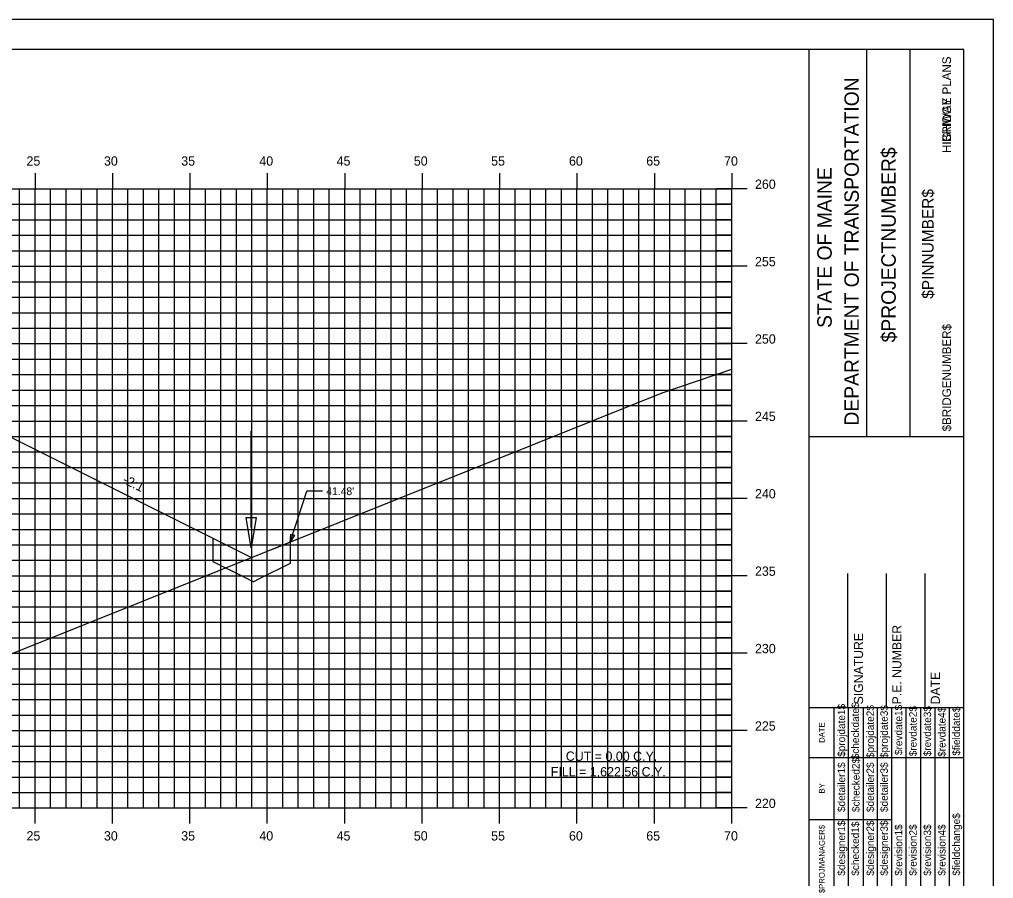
# Model space of a CAD drawing. Extents: x 1160718 to 1173142, y 616002 to 617630.
# Drawn here: x 1169986.4 to 1170049.3, y 616668.4 to 616723.9 of the extents above; entities that cross this region are included whole.
import ezdxf

# ---------------------------------------------------------------- set-up
doc = ezdxf.new("R2010")
doc.units = 0
for name, color, linetype in [('ANNOTATION', 7, 'Continuous'), ('BORDER', 7, 'Continuous'), ('BRIDGE_TITLE', 7, 'Continuous'), ('D_Drainage_Ditch_Line', 7, 'Continuous'), ('D_Roadway_SubGrade', 7, 'Continuous'), ('H_V ANNOTATION', 7, 'Continuous'), ('HIGHWAY_TITLE', 7, 'Continuous'), ('MAJOR', 7, 'Continuous'), ('MINOR', 7, 'Continuous'), ('PLOT BOUNDARY', 7, 'Continuous'), ('S_Roadway_Centerline', 7, 'Continuous')]:
    doc.layers.add(name, color=color, linetype=linetype)

msp = doc.modelspace()

# ---------------------------------------------------------------- linework, layer by layer
at = {"layer": 'ANNOTATION'}
for p in [(1170003.869, 616690.109), (1170005.953, 616693.39)]:
    msp.add_line(p, (1170004.953, 616693.39), dxfattribs=at)
for points in [[(1169998.869, 616690.357), (1170001.369, 616689.107), (1170003.869, 616690.109), (1170003.869, 616688.726), (1170001.869, 616687.726), (1170001.5, 616687.541)], [(1169998.869, 616690.357), (1169998.869, 616688.857), (1170000.869, 616687.857), (1170001.5, 616687.541)]]:
    msp.add_lwpolyline(points, dxfattribs=at)
msp.add_lwpolyline([(1170004.144, 616690.545), (1170003.869, 616690.109), (1170003.907, 616690.623)], close=True, dxfattribs=at)
at = {"layer": 'BORDER'}
for p, q in [((1170047.394, 616721.928), (1169887.394, 616721.928)), ((1170037.394, 616616.931), (1170037.394, 616721.931)), ((1170041.123, 616696.925), (1170041.123, 616721.925)), ((1170043.918, 616696.925), (1170043.918, 616721.925)), ((1170047.394, 616616.931), (1170047.394, 616721.931)), ((1170037.395, 616696.923), (1170047.394, 616696.923)), ((1170039.894, 616679.431), (1170039.894, 616688.079)), ((1170042.394, 616679.431), (1170042.394, 616688.079)), ((1170044.894, 616679.431), (1170044.894, 616688.079)), ((1170037.394, 616679.431), (1170047.394, 616679.431))]:
    msp.add_line(p, q, dxfattribs=at)
for points in [[(1170039.009, 616676.181), (1170039.009, 616679.431)], [(1170039.942, 616661.934), (1170039.942, 616679.431)], [(1170040.873, 616679.431), (1170040.873, 616661.934)], [(1170041.805, 616661.934), (1170041.805, 616679.431)], [(1170042.737, 616661.934), (1170042.737, 616679.431)], [(1170043.668, 616661.934), (1170043.668, 616679.431)], [(1170044.6, 616661.934), (1170044.6, 616679.431)], [(1170045.532, 616661.934), (1170045.532, 616679.431)], [(1170046.463, 616661.934), (1170046.463, 616679.431)], [(1170039.01, 616661.934), (1170039.01, 616678.725)], [(1170037.394, 616676.181), (1170047.394, 616676.181)], [(1170037.394, 616672.181), (1170039.01, 616672.181)], [(1170039.009, 616672.181), (1170042.736, 616672.181)]]:
    msp.add_lwpolyline(points, dxfattribs=at)
at = {"layer": 'D_Drainage_Ditch_Line'}
msp.add_line((1170001.346, 616691.04), (1170001.347, 616697.283), dxfattribs=at)
msp.add_lwpolyline([(1170001.018, 616691.696), (1170001.675, 616691.696), (1170001.347, 616689.727)], close=True, dxfattribs=at)
at = {"layer": 'D_Roadway_SubGrade'}
msp.add_line((1169982.394, 616698.594), (1170001.369, 616689.107), dxfattribs=at)
at = {"layer": 'MAJOR'}
for p, q in [((1169987.394, 616713.93), (1169987.394, 616712.928)), ((1169992.394, 616713.93), (1169992.394, 616712.928)), ((1169997.394, 616713.93), (1169997.394, 616712.928)), ((1170002.394, 616713.93), (1170002.394, 616712.928)), ((1170007.394, 616713.93), (1170007.394, 616712.928)), ((1170012.394, 616713.93), (1170012.394, 616712.928)), ((1170017.394, 616713.93), (1170017.394, 616712.928)), ((1170022.394, 616713.93), (1170022.394, 616712.928)), ((1170027.394, 616713.93), (1170027.394, 616712.928)), ((1170032.394, 616713.93), (1170032.394, 616712.928)), ((1169892.394, 616712.928), (1170032.394, 616712.928)), ((1169892.394, 616712.928), (1170032.394, 616712.928)), ((1169987.394, 616672.928), (1169987.394, 616712.928)), ((1169992.394, 616672.928), (1169992.394, 616712.928)), ((1169997.394, 616672.928), (1169997.394, 616712.928)), ((1170002.394, 616672.928), (1170002.394, 616712.928)), ((1170007.394, 616672.928), (1170007.394, 616712.928)), ((1170012.394, 616672.928), (1170012.394, 616712.928)), ((1170017.394, 616672.928), (1170017.394, 616712.928)), ((1170022.394, 616672.928), (1170022.394, 616712.928)), ((1170027.394, 616672.928), (1170027.394, 616712.928)), ((1170033.396, 616712.928), (1170031.392, 616712.928)), ((1170032.394, 616672.928), (1170032.394, 616712.928)), ((1170032.394, 616672.928), (1170032.394, 616712.928)), ((1169892.394, 616707.928), (1170032.394, 616707.928)), ((1170033.396, 616707.928), (1170031.392, 616707.928)), ((1169892.394, 616702.928), (1170032.394, 616702.928)), ((1170033.396, 616702.928), (1170031.392, 616702.928)), ((1169892.394, 616697.928), (1170032.394, 616697.928)), ((1170033.396, 616697.928), (1170031.392, 616697.928)), ((1169892.394, 616692.928), (1170032.394, 616692.928)), ((1170033.396, 616692.928), (1170031.392, 616692.928)), ((1169892.394, 616687.928), (1170032.394, 616687.928)), ((1170033.396, 616687.928), (1170031.392, 616687.928)), ((1169892.394, 616682.928), (1170032.394, 616682.928)), ((1170033.396, 616682.928), (1170031.392, 616682.928)), ((1169892.394, 616677.928), (1170032.394, 616677.928)), ((1170033.396, 616677.928), (1170031.392, 616677.928)), ((1169892.394, 616672.928), (1170032.394, 616672.928)), ((1169892.394, 616672.928), (1170032.394, 616672.928)), ((1169987.394, 616671.926), (1169987.394, 616672.928)), ((1169992.394, 616671.926), (1169992.394, 616672.928)), ((1169997.394, 616671.926), (1169997.394, 616672.928)), ((1170002.394, 616671.926), (1170002.394, 616672.928)), ((1170007.394, 616671.926), (1170007.394, 616672.928)), ((1170012.394, 616671.926), (1170012.394, 616672.928)), ((1170017.394, 616671.926), (1170017.394, 616672.928)), ((1170022.394, 616671.926), (1170022.394, 616672.928)), ((1170027.394, 616671.926), (1170027.394, 616672.928)), ((1170033.396, 616672.928), (1170031.392, 616672.928)), ((1170032.394, 616671.926), (1170032.394, 616672.928))]:
    msp.add_line(p, q, dxfattribs=at)
at = {"layer": 'MINOR'}
for p, q in [((1169986.394, 616672.928), (1169986.394, 616712.928)), ((1169988.394, 616672.928), (1169988.394, 616712.928)), ((1169989.394, 616672.928), (1169989.394, 616712.928)), ((1169990.394, 616672.928), (1169990.394, 616712.928)), ((1169991.394, 616672.928), (1169991.394, 616712.928)), ((1169993.394, 616672.928), (1169993.394, 616712.928)), ((1169994.394, 616672.928), (1169994.394, 616712.928)), ((1169995.394, 616672.928), (1169995.394, 616712.928)), ((1169996.394, 616672.928), (1169996.394, 616712.928)), ((1169998.394, 616672.928), (1169998.394, 616712.928)), ((1169999.394, 616672.928), (1169999.394, 616712.928)), ((1170000.394, 616672.928), (1170000.394, 616712.928)), ((1170001.394, 616672.928), (1170001.394, 616712.928)), ((1170003.394, 616672.928), (1170003.394, 616712.928)), ((1170004.394, 616672.928), (1170004.394, 616712.928)), ((1170005.394, 616672.928), (1170005.394, 616712.928)), ((1170006.394, 616672.928), (1170006.394, 616712.928)), ((1170008.394, 616672.928), (1170008.394, 616712.928)), ((1170009.394, 616672.928), (1170009.394, 616712.928)), ((1170010.394, 616672.928), (1170010.394, 616712.928)), ((1170011.394, 616672.928), (1170011.394, 616712.928)), ((1170013.394, 616672.928), (1170013.394, 616712.928)), ((1170014.394, 616672.928), (1170014.394, 616712.928)), ((1170015.394, 616672.928), (1170015.394, 616712.928)), ((1170016.394, 616672.928), (1170016.394, 616712.928)), ((1170018.394, 616672.928), (1170018.394, 616712.928)), ((1170019.394, 616672.928), (1170019.394, 616712.928)), ((1170020.394, 616672.928), (1170020.394, 616712.928)), ((1170021.394, 616672.928), (1170021.394, 616712.928)), ((1170023.394, 616672.928), (1170023.394, 616712.928)), ((1170024.394, 616672.928), (1170024.394, 616712.928)), ((1170025.394, 616672.928), (1170025.394, 616712.928)), ((1170026.394, 616672.928), (1170026.394, 616712.928)), ((1170028.394, 616672.928), (1170028.394, 616712.928)), ((1170029.394, 616672.928), (1170029.394, 616712.928)), ((1170030.394, 616672.928), (1170030.394, 616712.928)), ((1170031.394, 616672.928), (1170031.394, 616712.928)), ((1169892.394, 616711.928), (1170032.394, 616711.928)), ((1170032.394, 616711.928), (1170031.392, 616711.928)), ((1169892.394, 616710.928), (1170032.394, 616710.928)), ((1170032.394, 616710.928), (1170031.392, 616710.928)), ((1169892.394, 616709.928), (1170032.394, 616709.928)), ((1170032.394, 616709.928), (1170031.392, 616709.928)), ((1169892.394, 616708.928), (1170032.394, 616708.928)), ((1170032.394, 616708.928), (1170031.392, 616708.928)), ((1169892.394, 616706.928), (1170032.394, 616706.928)), ((1170032.394, 616706.928), (1170031.392, 616706.928)), ((1169892.394, 616705.928), (1170032.394, 616705.928)), ((1170032.394, 616705.928), (1170031.392, 616705.928)), ((1169892.394, 616704.928), (1170032.394, 616704.928)), ((1170032.394, 616704.928), (1170031.392, 616704.928)), ((1169892.394, 616703.928), (1170032.394, 616703.928)), ((1170032.394, 616703.928), (1170031.392, 616703.928)), ((1169892.394, 616701.928), (1170032.394, 616701.928)), ((1170032.394, 616701.928), (1170031.392, 616701.928)), ((1169892.394, 616700.928), (1170032.394, 616700.928)), ((1170032.394, 616700.928), (1170031.392, 616700.928)), ((1169892.394, 616699.928), (1170032.394, 616699.928)), ((1170032.394, 616699.928), (1170031.392, 616699.928)), ((1169892.394, 616698.928), (1170032.394, 616698.928)), ((1170032.394, 616698.928), (1170031.392, 616698.928)), ((1169892.394, 616696.928), (1170032.394, 616696.928)), ((1170032.394, 616696.928), (1170031.392, 616696.928)), ((1169892.394, 616695.928), (1170032.394, 616695.928)), ((1170032.394, 616695.928), (1170031.392, 616695.928)), ((1169892.394, 616694.928), (1170032.394, 616694.928)), ((1170032.394, 616694.928), (1170031.392, 616694.928)), ((1169892.394, 616693.928), (1170032.394, 616693.928)), ((1170032.394, 616693.928), (1170031.392, 616693.928)), ((1169892.394, 616691.928), (1170032.394, 616691.928)), ((1170032.394, 616691.928), (1170031.392, 616691.928)), ((1169892.394, 616690.928), (1170032.394, 616690.928)), ((1170032.394, 616690.928), (1170031.392, 616690.928)), ((1169892.394, 616689.928), (1170032.394, 616689.928)), ((1170032.394, 616689.928), (1170031.392, 616689.928)), ((1169892.394, 616688.928), (1170032.394, 616688.928)), ((1170032.394, 616688.928), (1170031.392, 616688.928)), ((1169892.394, 616686.928), (1170032.394, 616686.928)), ((1170032.394, 616686.928), (1170031.392, 616686.928)), ((1169892.394, 616685.928), (1170032.394, 616685.928)), ((1170032.394, 616685.928), (1170031.392, 616685.928)), ((1169892.394, 616684.928), (1170032.394, 616684.928)), ((1170032.394, 616684.928), (1170031.392, 616684.928)), ((1169892.394, 616683.928), (1170032.394, 616683.928)), ((1170032.394, 616683.928), (1170031.392, 616683.928)), ((1169892.394, 616681.928), (1170032.394, 616681.928)), ((1170032.394, 616681.928), (1170031.392, 616681.928)), ((1169892.394, 616680.928), (1170032.394, 616680.928)), ((1170032.394, 616680.928), (1170031.392, 616680.928)), ((1169892.394, 616679.928), (1170032.394, 616679.928)), ((1170032.394, 616679.928), (1170031.392, 616679.928)), ((1169892.394, 616678.928), (1170032.394, 616678.928)), ((1170032.394, 616678.928), (1170031.392, 616678.928)), ((1169892.394, 616676.928), (1170032.394, 616676.928)), ((1170032.394, 616676.928), (1170031.392, 616676.928)), ((1169892.394, 616675.928), (1170032.394, 616675.928)), ((1170032.394, 616675.928), (1170031.392, 616675.928)), ((1169892.394, 616674.928), (1170032.394, 616674.928)), ((1170032.394, 616674.928), (1170031.392, 616674.928)), ((1169892.394, 616673.928), (1170032.394, 616673.928)), ((1170032.394, 616673.928), (1170031.392, 616673.928))]:
    msp.add_line(p, q, dxfattribs=at)
at = {"layer": 'PLOT BOUNDARY'}
msp.add_lwpolyline([(1169879.301, 616613.869), (1170049.301, 616613.869), (1170049.301, 616723.869), (1169879.301, 616723.869)], close=True, dxfattribs=at)
at = {"layer": 'S_Roadway_Centerline'}
msp.add_lwpolyline([(1169892.394, 616704.998), (1169908.245, 616697.269), (1169915.124, 616693.694), (1169944.356, 616683.254), (1169956.998, 616682.309), (1169964.821, 616682.573), (1169971.903, 616683.316), (1169981.644, 616681.197), (1170027.895, 616699.745), (1170032.394, 616701.285)], dxfattribs=at)

# ---------------------------------------------------------------- texts
at = {"layer": 'ANNOTATION'}
for s, rotation, p in [('-2:1', 333.43495, (1169993.005, 616693.951)), ('CUT = 0.00 C.Y.', 359.92408, (1170021.674, 616675.978)), ('FILL = 1,622.56 C.Y.', 359.92408, (1170020.704, 616674.977))]:
    msp.add_text(s, height=0.6, rotation=rotation, dxfattribs=at).set_placement(p)
msp.add_text("41.48'", height=0.5, dxfattribs=at).set_placement((1170006.203, 616693.14))
at = {"layer": 'BORDER'}
for s, height, p in [('DEPARTMENT OF TRANSPORTATION', 0.93176, (1170040.601, 616697.634)), ('$PROJECTNUMBER$', 0.93176, (1170042.986, 616703.008)), ('STATE OF MAINE', 0.93176, (1170038.849, 616703.94)), ('$PINNUMBER$', 0.74527, (1170045.431, 616705.825)), ('P.E. NUMBER', 0.59055, (1170043.355, 616679.624)), ('SIGNATURE', 0.5906, (1170040.875, 616679.624)), ('DATE', 0.5906, (1170045.835, 616679.624)), ('$projdate1$', 0.48455, (1170039.717, 616676.232)), ('$checkdate$', 0.48455, (1170040.612, 616676.074)), ('$projdate2$', 0.48455, (1170041.58, 616676.153)), ('$projdate3$', 0.48455, (1170042.475, 616676.153)), ('$revdate1$', 0.4845, (1170043.407, 616676.35)), ('$revdate2$', 0.4845, (1170044.338, 616676.271)), ('$revdate3$', 0.4845, (1170045.27, 616676.271)), ('$revdate4$', 0.4845, (1170046.202, 616676.232)), ('$fielddate$', 0.48455, (1170047.133, 616676.31)), ('DATE', 0.3714, (1170038.398, 616677.137)), ('$detailer1$', 0.48455, (1170039.717, 616672.667)), ('$checked2$', 0.4845, (1170040.649, 616672.667)), ('$detailer2$', 0.48455, (1170041.58, 616672.667)), ('$detailer3$', 0.48455, (1170042.475, 616672.667)), ('BY', 0.3714, (1170038.398, 616673.866)), ('$fieldchange$', 0.48455, (1170047.133, 616668.555)), ('$PROJMANAGER$', 0.37275, (1170038.398, 616667.426)), ('$designer1$', 0.48455, (1170039.717, 616668.555)), ('$checked1$', 0.4845, (1170040.612, 616668.555)), ('$designer2$', 0.48455, (1170041.58, 616668.555)), ('$designer3$', 0.48455, (1170042.475, 616668.555)), ('$revision1$', 0.48455, (1170043.407, 616668.555)), ('$revision2$', 0.48455, (1170044.338, 616668.555)), ('$revision3$', 0.48455, (1170045.27, 616668.555)), ('$revision4$', 0.48455, (1170046.202, 616668.555))]:
    msp.add_text(s, height=height, rotation=90, dxfattribs=at).set_placement(p)
at = {"layer": 'BRIDGE_TITLE'}
for s, p in [('BRIDGE PLANS', (1170046.552, 616715.953)), ('$BRIDGENUMBER$', (1170046.552, 616697.259))]:
    msp.add_text(s, height=0.55901, rotation=90, dxfattribs=at).set_placement(p)
at = {"layer": 'H_V ANNOTATION'}
for s, p in [('25', (1169986.84, 616714.428)), ('30', (1169991.843, 616714.428)), ('35', (1169996.835, 616714.428)), ('40', (1170001.88, 616714.428)), ('45', (1170006.872, 616714.428)), ('50', (1170011.859, 616714.428)), ('55', (1170016.851, 616714.428)), ('60', (1170021.88, 616714.428)), ('65', (1170026.872, 616714.428)), ('70', (1170031.896, 616714.428)), ('260', (1170033.894, 616712.928)), ('255', (1170033.894, 616707.928)), ('250', (1170033.894, 616702.928)), ('245', (1170033.894, 616697.928)), ('240', (1170033.894, 616692.928)), ('235', (1170033.894, 616687.928)), ('230', (1170033.894, 616682.928)), ('225', (1170033.894, 616677.928)), ('220', (1170033.894, 616672.928)), ('25', (1169986.84, 616670.828)), ('30', (1169991.843, 616670.828)), ('35', (1169996.835, 616670.828)), ('40', (1170001.88, 616670.828)), ('45', (1170006.872, 616670.828)), ('50', (1170011.859, 616670.828)), ('55', (1170016.851, 616670.828)), ('60', (1170021.88, 616670.828)), ('65', (1170026.872, 616670.828)), ('70', (1170031.896, 616670.828))]:
    msp.add_text(s, height=0.6, dxfattribs=at).set_placement(p)
at = {"layer": 'HIGHWAY_TITLE'}
msp.add_text('HIGHWAY PLANS', height=0.55901, rotation=90, dxfattribs=at).set_placement((1170046.552, 616715.244))

doc.saveas('drawing.dxf')
